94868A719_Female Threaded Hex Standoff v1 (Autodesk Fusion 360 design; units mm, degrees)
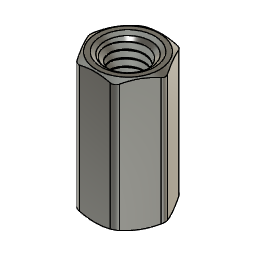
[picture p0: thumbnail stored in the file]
description: STEP AP203
part number: 94868A719_Female Threaded Hex Standoff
